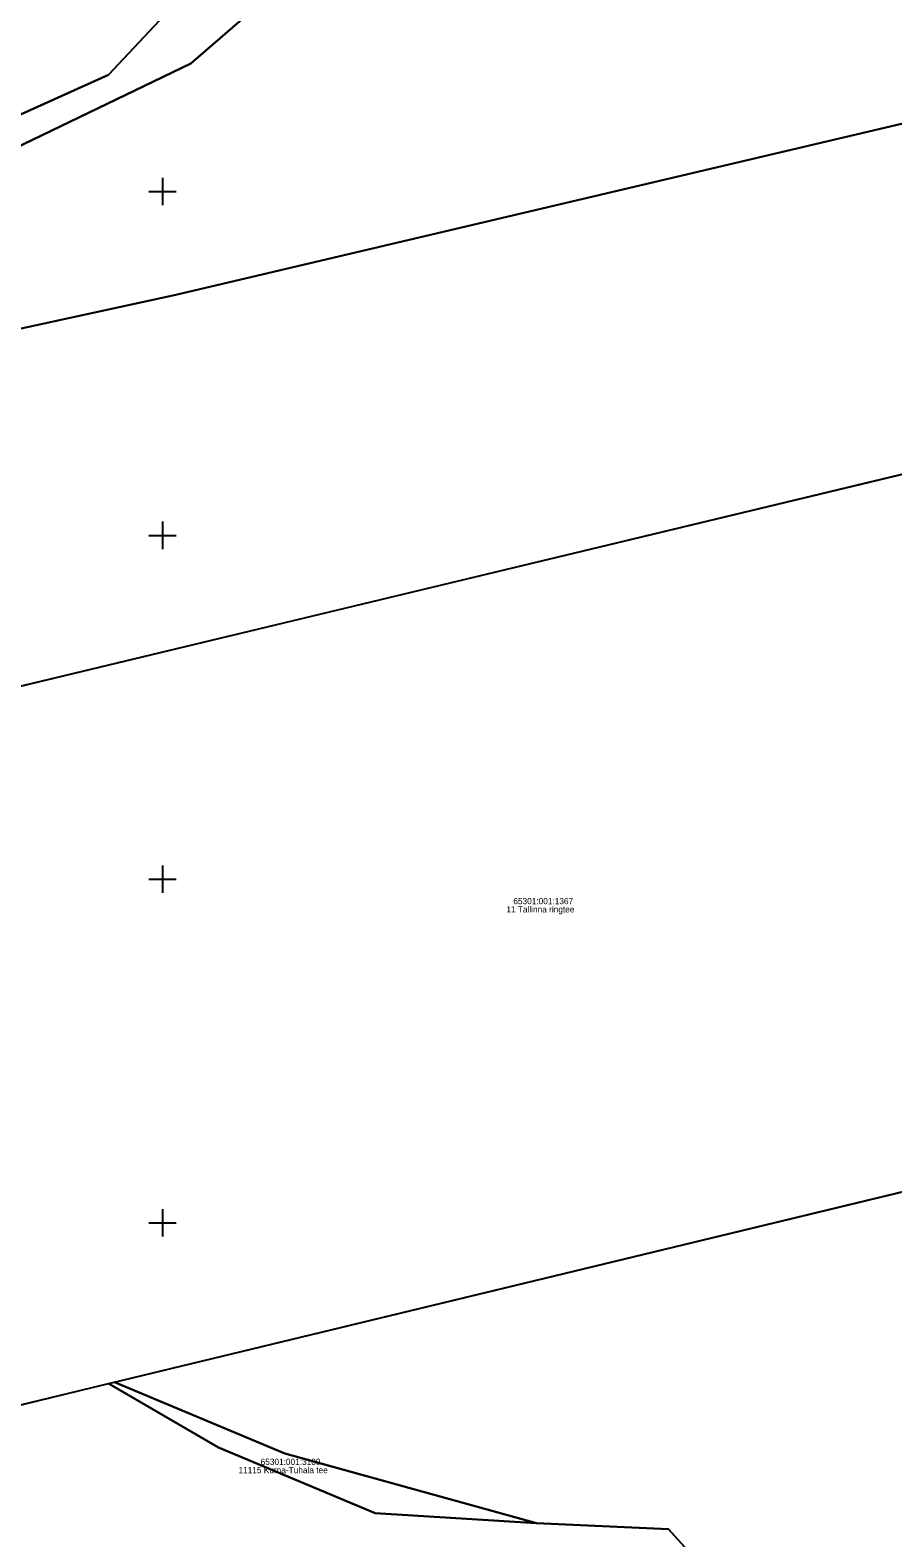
# Model space of a CAD drawing. Extents: x 543497 to 552146, y 6567125 to 6579845.
# Drawn here: x 546780.8 to 546906.2, y 6577704.2 to 6577923.5 of the extents above; entities that cross this region are included whole.
import ezdxf

# ---------------------------------------------------------------- set-up
doc = ezdxf.new("R2010")
doc.units = 0
doc.layers.add('xref_Kangru tee 1_geodeesia$0$PIIR', color=7, linetype='Continuous')
doc.layers.add('xref_Kangru tee 1_geodeesia$0$vork', color=7, linetype='Continuous')

# ---------------------------------------------------------------- blocks, each defined once
blk = doc.blocks.new('xref_Kangru tee 1_geodeesia$0$VKORIS')
for p, q in [((-4, 0), (4, 0)), ((0, 4), (0, -4))]:
    blk.add_line(p, q)

msp = doc.modelspace()

# ---------------------------------------------------------------- linework, layer by layer
at = {"layer": 'xref_Kangru tee 1_geodeesia$0$PIIR'}
for points in [[(546948.2, 6577919.45), (546801.95, 6577884.96), (546612.83, 6577843.82), (546611.48, 6577846.34), (546681.56, 6577865.74), (546741.83, 6577888.61), (546804.12, 6577918.64), (546823.72, 6577935.62), (546840.87, 6577968.94), (546842.58, 6578000.95), (546830.7, 6578057.64), (546794.77, 6578166.4), (546728.27, 6578308.16), (546677.39, 6578395.18), (546581.04, 6578525.99)], [(546479.96, 6578264.05), (546660.75, 6578417.77), (546677.39, 6578395.18), (546728.27, 6578308.16), (546794.77, 6578166.4), (546830.7, 6578057.64), (546842.58, 6578000.95), (546840.87, 6577968.94), (546792.14, 6577916.99), (546673.57, 6577863.53), (546611.48, 6577846.34), (546521.16, 6578099.75), (546496.8, 6578164.74), (546476.38, 6578219.21), (546479.96, 6578264.05)], [(546673.57, 6577863.53), (546792.14, 6577916.99), (546840.87, 6577968.94), (546823.72, 6577935.62), (546804.12, 6577918.64), (546741.83, 6577888.61), (546681.56, 6577865.74), (546673.57, 6577863.53)], [(547009.94, 6577883.45), (546729.34, 6577816.03), (546702.66, 6577807.95), (546633.51, 6577792.62), (546622.52, 6577814.88), (546612.83, 6577843.82), (546801.95, 6577884.96), (546948.2, 6577919.45)], [(546729.34, 6577816.03), (546952.06, 6577869.63), (546981.71, 6577772.45), (546959.14, 6577767.02), (546924.09, 6577758.51), (546773.43, 6577722.06), (546729.34, 6577816.03)], [(546793.02, 6577726.81), (546924.09, 6577758.51), (546926.96, 6577717.37), (546926.35, 6577656.17), (546919.08, 6577563.55), (546904.61, 6577476.08), (546854.32, 6577459.54), (546854.62, 6577460.98), (546872.38, 6577554.26), (546881.53, 6577696.65), (546873.59, 6577705.44), (546854.37, 6577706.34), (546817.78, 6577716.43), (546793.02, 6577726.81)], [(546792.14, 6577726.64), (546793.02, 6577726.81), (546817.78, 6577716.43), (546854.37, 6577706.34), (546830.92, 6577707.77), (546808.12, 6577717.32), (546792.14, 6577726.64)], [(546854.62, 6577460.98), (546809.92, 6577515.54), (546792.48, 6577521.35), (546790.29, 6577520.39), (546720.35, 6577605.39), (546691.87, 6577664.79), (546676.52, 6577698.59), (546773.43, 6577722.06), (546792.14, 6577726.64), (546808.12, 6577717.32), (546830.92, 6577707.77), (546854.37, 6577706.34), (546873.59, 6577705.44), (546881.53, 6577696.65), (546872.38, 6577554.26), (546854.62, 6577460.98)]]:
    msp.add_lwpolyline(points, dxfattribs=at)

# ---------------------------------------------------------------- block references
at = {"layer": 'xref_Kangru tee 1_geodeesia$0$vork', "xscale": 0.5, "yscale": 0.5}
for p in [(546800, 6577900), (546800, 6577850), (546800, 6577800), (546800, 6577750)]:
    msp.add_blockref('xref_Kangru tee 1_geodeesia$0$VKORIS', p, dxfattribs=at)

# ---------------------------------------------------------------- texts
at = {"layer": 'xref_Kangru tee 1_geodeesia$0$PIIR'}
for s, p in [('65301:001:1367', (546851.02, 6577796.35)), ('11 Tallinna ringtee', (546850.01, 6577795.15)), ('11115 Kurna-Tuhala tee', (546811.05, 6577713.59)), ('65301:001:3109', (546814.27, 6577714.79))]:
    msp.add_text(s, height=0.9, dxfattribs=at).set_placement(p)

doc.saveas('drawing.dxf')
